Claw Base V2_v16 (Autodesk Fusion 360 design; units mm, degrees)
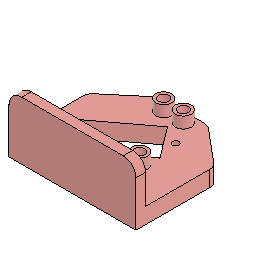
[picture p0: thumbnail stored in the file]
sketch "Sketch1" plane through (0, 0, 0) normal (0, 0, 1) x axis (1, 0, 0)
  line L1 (-20, -17.5) -> (20, -17.5)
  line L2 (-20, 17.5) -> (-20, -17.5)
  line L3 (20, 17.5) -> (-20, 17.5)
  line L4 (20, -17.5) -> (20, 17.5)
  line L5 (-20, 17.5) -> (20, -17.5)
  line L6 (20, 17.5) -> (-20, -17.5)
  line L7 (0, -17.5) -> (0, 17.5)
  line L8 (4.0769, -16) -> (-3.2529, -16)
  line L9 (-20, -17.5) -> (20, -17.5)
  line L10 (-20, -14.5) -> (-20, -17.5)
  line L11 (20, -14.5) -> (-20, -14.5)
  line L12 (20, -17.5) -> (20, -14.5)
  line L13 (-20, -14.5) -> (20, -17.5)
  line L14 (20, -14.5) -> (-20, -17.5)
  line L15 (7.7, -17.5) -> (7.7, 17.5)
  line L16 (-7.7, -17.5) -> (-7.7, 17.5)
  line L17 (20, 14.33) -> (-20, 14.33)
  line L18 (20, -4) -> (-20, -4)
  line L19 (-7.0975, -14.7693) -> (-16.1328, -2.7791)
  line L20 (-7.1761, 3.9702) -> (-16.1328, -2.7791)
  line L21 (-8.6616, -12.6938) -> (-16.1328, -2.7791)
  line L22 (-8.8508, -12.4426) -> (-16.1328, -2.7791)
  line L23 (9.0386, 1.038) -> (-8.8508, -12.4426)
  line L24 (1.7566, 10.7015) -> (9.0386, 1.038)
  line L25 (-16.1328, -2.7791) -> (1.7566, 10.7015)
  line L26 (12.5021, 11.2234) -> (5.3976, 5.8698)
  line L27 (-16.1516, -10.3687) -> (-12.4918, -7.6109)
  line L28 (-20, 7.1791) -> (-7.7, 17.5)
  line L29 (8.3565, 17.5) -> (-7.7, 17.5)
  line L30 (20.0608, 7.1281) -> (7.7, 17.5)
  line L31 (23.8359, 17.5) -> (7.7, 17.5)
  circle C1 centre (7.7, -4) radius 1.6
  circle C2 centre (7.7, -4) radius 7.7
  circle C3 centre (-7.7, -4) radius 7.7
  circle C4 centre (-3.1, 14.33) radius 1.6
  circle C5 centre (3.1, 14.33) radius 1.6
  circle C6 centre (7.7, -4) radius 2.5
  circle C7 centre (7.5539, 7.4947) radius 1
  circle C8 centre (-14.6481, -9.2358) radius 1
  point P6 (0, 0)
  point P1 (0, 0)
  point P7 (0, 17.5)
  point P8 (0, -17.5)
  point P15 (0, -16)
  point P16 (7.7, 17.5)
  point P17 (7.7, -17.5)
  point P18 (-7.7, 17.5)
  point P19 (-7.7, -17.5)
  point P20 (-20, 14.33)
  point P21 (20, 14.33)
  point P22 (-20, -4)
  point P23 (20, -4)
  point P24 (7.7, -4)
  point P26 (-7.7, -4)
  point P27 (-3.1, 14.33)
  point P37 (5.3976, 5.8698)
  point P39 (7.5539, 7.4947)
  point P40 (-12.4918, -7.6109)
  point P42 (-14.6481, -9.2358)
  point P43 (-20, 7.1791)
  point P4 (-20, 17.5)
  point P5 (20, 17.5)
  point P3 (-20, -17.5)
  point P12 (-20, -17.5)
  point P13 (-20, -14.5)
  point P14 (20, -14.5)
  point P30 (-16.1328, -2.7791)
  point P36 (1.7566, 10.7015)
  horizontal L1
  perpendicular L1 L2
  parallel L1 L3
  parallel L2 L4
  coincident L5 P6
  coincident L6 P6
  coincident P1 P6
  midpoint L3 P7
  midpoint L1 P8
  horizontal L8
  horizontal L9
  perpendicular L9 L10
  parallel L9 L11
  parallel L10 L12
  coincident L13 P15
  coincident L14 P15
  coincident L8 P15
  coincident L7 P15
  coincident L3 P16
  coincident L9 P17
  perpendicular L9 L15
  coincident L3 P18
  coincident L9 P19
  perpendicular L9 L16
  coincident L2 P20
  coincident L4 P21
  perpendicular L4 L17
  coincident L2 P22
  coincident L4 P23
  perpendicular L4 L18
  coincident L18 P24
  coincident L15 P24
  concentric C1 C2
  coincident L18 P26
  coincident L16 P26
  coincident L17 P27
  symmetric L7 C4 C5
  concentric C1 C6
  perpendicular L19 L20
  perpendicular L20 L21
  perpendicular L22 L23
  parallel L22 L24
  parallel L23 L25
  perpendicular L20 L22
  midpoint L24 P37
  perpendicular L24 L26
  coincident L26 P39
  midpoint L22 P40
  perpendicular L21 L27
  coincident L27 P42
  horizontal L29
  coincident L2 P43
  horizontal L31
  dimension "d1" distance P4 P5 = 40
  dimension "d2" distance P3 P4 = 35
  dimension "d3" distance L1 L8 = 1.5
  dimension "d5" distance P12 P13 = 3
  dimension "d6" distance L7 L15 = 7.7 (= "( 15.4 / 2 ) * 1 mm")
  dimension "d7" distance L7 L16 = 7.7 (= "d6")
  dimension "d14" distance L11 L18 = 10.5
  dimension "d15" diameter C1 = 3.2
  dimension "d16" diameter C2 = 15.4
  dimension "d17" diameter C3 = 15.4
  dimension "d18" distance L17 L18 = 18.33
  dimension "d29" diameter C4 = 3.2
  dimension "d30" distance L7 P27 = 3.1
  dimension "d42" distance P13 P14 = 40 (= "d1")
  dimension "d49" diameter C6 = 5
  dimension "d68" angle L18 L19 = 127 (= "180 deg - 53 deg")
  dimension "d69" distance P26 L19 = 6
  dimension "d70" distance P26 L20 = 6.05 (= "( 12.10 / 2 ) * 1 mm")
  dimension "d79" distance P30 P36 = 22.4
  dimension "d81" diameter C7 = 2 (= "d87")
  dimension "d82" distance L24 P39 = 2.7 (= "d88")
  dimension "d87" diameter C8 = 2
  dimension "d88" distance L19 P42 = 2.7 (= "4.7 mm + 0.3 mm - 2.3 mm")
  dimension "d89" angle L28 L29 = 140
  dimension "d90" angle L30 L31 = 40
extrude "Extrude1" new body sketch "Sketch1" profile of L2 L3 L4 L11 C1 C4 C5 C6 L21 L22 L23 L24 L25 C7 C8 L28 L30 along normal blind 5
extrude "Extrude2" add sketch "Sketch1" profile of L1 L2 L4 L9 L10 L11 L12 along normal blind 18.3
sketch "Sketch3" plane through (0, 0, 5) normal (0, 0, 1) x axis (-1, 0, 0)
  line L1 (20, 14.5) -> (20, -7.1791)
  line L2 (-20, -7.1791) -> (-20, 14.5)
  line L3 (7.7, -17.5) -> (-7.7, -17.5)
  line L4 (-1.7566, -10.7015) -> (16.1328, 2.7791)
  line L5 (-9.0386, -1.038) -> (-1.7566, -10.7015)
  line L6 (8.8508, 12.4426) -> (-9.0386, -1.038)
  line L7 (16.1328, 2.7791) -> (8.8508, 12.4426)
  line L8 (20, -7.1791) -> (7.7, -17.5)
  line L9 (-7.7, -17.5) -> (-20, -7.1791)
  line L10 (-20, 14.5) -> (20, 14.5)
  circle C1 centre (-7.7, 4) radius 1.6
  circle C2 centre (-3.1, -14.33) radius 1.6
  circle C3 centre (3.1, -14.33) radius 1.6
  circle C4 centre (-7.7, 4) radius 2.5
  circle C5 centre (-3.1, -14.33) radius 2.5
  circle C6 centre (3.1, -14.33) radius 2.5
  circle C7 centre (-7.5539, -7.4947) radius 1
  circle C8 centre (14.6481, 9.2358) radius 1
  concentric C1 C4
  concentric C2 C5
  concentric C3 C6
  dimension "d50" diameter C4 = 5
  dimension "d53" diameter C5 = 5
  dimension "d54" diameter C6 = 5
extrude "Extrude3" add sketch "Sketch3" profile of C1 C2 C3 C4 C5 C6 along normal blind 3.55 (= "2.55 mm + 1 mm")
fillet "Fillet2" radius 4
fillet "Fillet3" radius 3
fillet "Fillet4" radius 4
